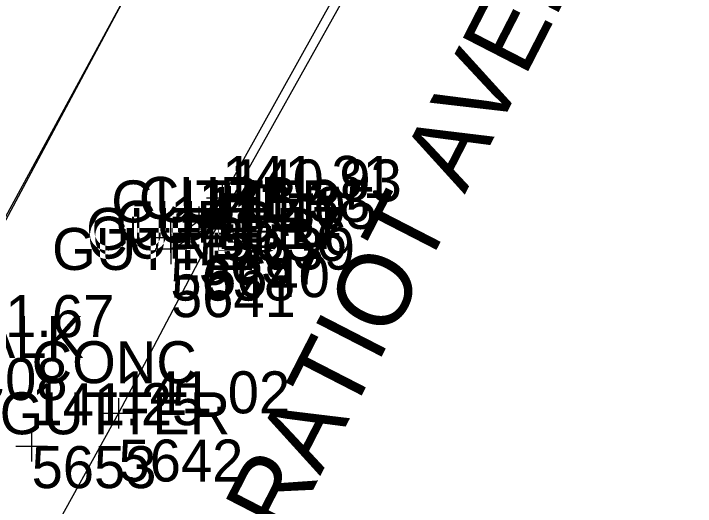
# Model space of a CAD drawing. Extents: x 13482495 to 13483389, y 311646 to 312209.
# Drawn here: x 13483245.5 to 13483297.5, y 311982.2 to 312019.7 of the extents above; entities that cross this region are included whole.
import ezdxf

# ---------------------------------------------------------------- set-up
doc = ezdxf.new("R2010")
doc.units = 0
for name, color, linetype in [('V-ANNO-TEXT', 7, 'Continuous'), ('V-PROP-RWAY', 7, 'Continuous'), ('V-PVMT-BACK', 7, 'Continuous'), ('V-PVMT-ROAD', 7, 'Continuous'), ('V-PVMT-SPOT', 7, 'Continuous'), ('V-SITE-IDEN', 7, 'Continuous'), ('V-SITE-SPOT', 7, 'Continuous'), ('V-SITE-WALK', 7, 'Continuous'), ('V-SURV-PNTS', 7, 'Continuous'), ('V-TOPO-LINE-IDEN', 7, 'Continuous')]:
    doc.layers.add(name, color=color, linetype=linetype)

msp = doc.modelspace()

# ---------------------------------------------------------------- linework, layer by layer
at = {"layer": 'V-PROP-RWAY'}
msp.add_line((13483192.658, 311908.098), (13483276.388, 312062.114), dxfattribs=at)
at = {"layer": 'V-PVMT-BACK'}
msp.add_lwpolyline([(13483265.367, 312065.469), (13483266.904, 312067.158), (13483268.711, 312068.553), (13483270.734, 312069.612), (13483272.91, 312070.302), (13483275.173, 312070.603), (13483277.454, 312070.505), (13483279.683, 312070.011), (13483279.844, 312069.959), (13483281.692, 312068.707), (13483283.459, 312067.111), (13483284.934, 312065.242), (13483286.077, 312063.153), (13483286.685, 312061.511), (13483287.334, 312059.111), (13483287.694, 312057.052), (13483287.657, 312054.963), (13483287.224, 312052.919), (13483286.819, 312051.835), (13483272.932, 312026.347), (13483261.444, 312005.675), (13483260.181, 312004.285), (13483258.653, 312003.194), (13483257.491, 312002.645)], dxfattribs=at)
at = {"layer": 'V-PVMT-ROAD'}
for points in [[(13483264.812, 312066.093), (13483266.499, 312067.784), (13483268.445, 312069.171), (13483270.595, 312070.215), (13483272.888, 312070.886), (13483275.261, 312071.165), (13483277.648, 312071.046), (13483279.981, 312070.531), (13483279.987, 312070.529), (13483281.988, 312069.166), (13483283.778, 312067.617), (13483285.281, 312065.789), (13483286.456, 312063.735), (13483287.215, 312061.702), (13483287.934, 312059.343), (13483288.263, 312057.108), (13483288.193, 312054.85), (13483287.727, 312052.639), (13483287.382, 312051.654), (13483273.552, 312025.959), (13483262.051, 312005.407), (13483253.537, 311989.252), (13483242.277, 311968.929), (13483232.654, 311951.179)], [(13483262.051, 312005.407), (13483260.781, 312003.887), (13483259.232, 312002.653), (13483257.538, 312001.782)]]:
    msp.add_lwpolyline(points, dxfattribs=at)
at = {"layer": 'V-PVMT-SPOT'}
for p, q in [((13483261.444, 312006.835), (13483261.444, 312004.515)), ((13483262.051, 312006.567), (13483262.051, 312004.247)), ((13483262.051, 312006.567), (13483262.051, 312004.247)), ((13483260.244, 312005.675), (13483262.644, 312005.675)), ((13483259.653, 312005.011), (13483259.653, 312002.691)), ((13483260.851, 312005.407), (13483263.251, 312005.407)), ((13483260.851, 312005.407), (13483263.251, 312005.407)), ((13483260.133, 312004.468), (13483260.133, 312002.148)), ((13483257.491, 312003.805), (13483257.491, 312001.485)), ((13483258.453, 312003.851), (13483260.853, 312003.851)), ((13483257.538, 312002.942), (13483257.538, 312000.622)), ((13483258.933, 312003.308), (13483261.333, 312003.308)), ((13483256.291, 312002.645), (13483258.691, 312002.645)), ((13483256.338, 312001.782), (13483258.738, 312001.782)), ((13483253.537, 311990.412), (13483253.537, 311988.092)), ((13483252.337, 311989.252), (13483254.737, 311989.252))]:
    msp.add_line(p, q, dxfattribs=at)
at = {"layer": 'V-SITE-SPOT'}
for p, q in [((13483246.907, 311987.907), (13483246.907, 311985.587)), ((13483245.707, 311986.747), (13483248.107, 311986.747))]:
    msp.add_line(p, q, dxfattribs=at)
at = {"layer": 'V-SITE-WALK'}
msp.add_lwpolyline([(13483219.99, 311958.205), (13483240.127, 311995.062), (13483265.094, 312041.637), (13483269.475, 312052.418), (13483267.261, 312057.854), (13483264.689, 312064.334), (13483265.367, 312065.469)], dxfattribs=at)

# ---------------------------------------------------------------- texts
at = {"layer": 'V-ANNO-TEXT'}
msp.add_text('GRATIOT AVE. (M-3)', height=5.6, rotation=62.8066, dxfattribs=at).set_placement((13483263.78, 311974.454))
at = {"layer": 'V-PVMT-SPOT'}
for s, p in [('141.31', (13483261.444, 312005.675)), ('140.93', (13483262.051, 312005.407)), ('140.93', (13483262.051, 312005.407)), ('141.38', (13483259.653, 312003.851)), ('141.05', (13483260.133, 312003.308)), ('141.41', (13483257.491, 312002.645)), ('141.17', (13483257.538, 312001.782)), ('141.67', (13483240.127, 311995.062)), ('141.02', (13483253.537, 311989.252))]:
    msp.add_text(s, height=3.2, dxfattribs=at).set_placement(p)
at = {"layer": 'V-SITE-IDEN'}
msp.add_text('CONC', height=3.2, dxfattribs=at).set_placement((13483246.907, 311991.547))
at = {"layer": 'V-SITE-SPOT'}
msp.add_text('141.25', height=3.2, dxfattribs=at).set_placement((13483246.907, 311988.347))
at = {"layer": 'V-SURV-PNTS'}
for s, p in [('5636', (13483261.444, 312000.875)), ('5639', (13483262.051, 312000.207)), ('5639', (13483262.051, 312000.207)), ('5637', (13483259.653, 311999.051)), ('5640', (13483260.133, 311998.108)), ('5638', (13483257.491, 311997.845)), ('5641', (13483257.538, 311996.582)), ('5608', (13483240.127, 311990.262)), ('5642', (13483253.537, 311984.052)), ('5653', (13483246.907, 311983.547))]:
    msp.add_text(s, height=3.2, dxfattribs=at).set_placement(p)
at = {"layer": 'V-TOPO-LINE-IDEN'}
for s, p in [('GUTTER', (13483252.98, 312003.807)), ('GUTTER', (13483252.98, 312003.807)), (' CURB', (13483253.898, 312004.075)), (' CURB', (13483252.107, 312002.251)), ('GUTTER', (13483251.062, 312001.708)), (' CURB', (13483249.944, 312001.045)), ('GUTTER', (13483248.467, 312000.182)), ('SIDEWALK', (13483228.777, 311993.462)), ('GUTTER', (13483244.467, 311987.652))]:
    msp.add_text(s, height=3.2, dxfattribs=at).set_placement(p)

doc.saveas('drawing.dxf')
